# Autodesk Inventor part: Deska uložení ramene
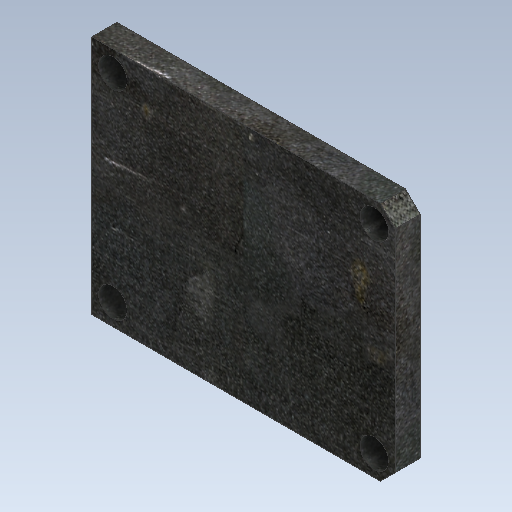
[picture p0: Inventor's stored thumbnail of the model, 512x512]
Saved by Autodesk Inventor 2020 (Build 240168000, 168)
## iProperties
Created: 2025-03
Part Number: Deska uložení ramene
Material: Ocel
Document SubType Name: Modeling
Designer: doma
Density: 7.85 g/cm^3
Appearance: Plech
Mass: 1512.23 g
Surface Area: 402.842 cm^2
Volume: 192.641 cm^3
Author: doma
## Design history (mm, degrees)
sketch "Náčrt1"
  geometry: L1 (0, 0)-(145, 0); L2 (145, 0)-(145, 115); L3 (145, 115)-(0, 115); L4 (0, 115)-(0, 0)
  constraints: 8 end point, 2 parallel, 1 horizontal, 1 perpendicular
  dimensions: "d0" = 145 distance of L3.end L2.end; "d1" = 115 distance of L2.end L1.end
extrude "Vysunutí1" new body sketch "Náčrt1" distance "d2" = 12; taper "d3" = 0 deg
chamfer "Zkosení1" distance "d4" = 7; stored, may be unused: second distance "d5" = 2, angle "d6" = 45 deg
sketch "Náčrt2" dims "d14" = 10, "d21" = 10
  geometry: L1 (0, 0)-(138, 0) reference; L2 (0, 115)-(0, 0) reference; 4 further points
  constraints: 1 horizontal, 1 vertical, 3 other
  dimensions: "d7" = 10 distance from line of L1 point (10, 10); "d8" = 10 distance from line of L2 point (10, 10); "d11" = 125 distance of point (10, 10) point (135, 10); "d18" = 95 distance of point (135, 10) point (135, 105)
hole "Díra1" sketch "Náčrt2" at (10, 10), (135, 10), (135, 105), (10, 105) diameter "d23" = 13.5; stored, may be unused: countersink angle "d27" = 90 deg, drill point angle "d29" = 118 deg; dims "d24" = 10, "d25" = 4, "d26" = 2, "d28" = 15.1
node "Těleso1"
